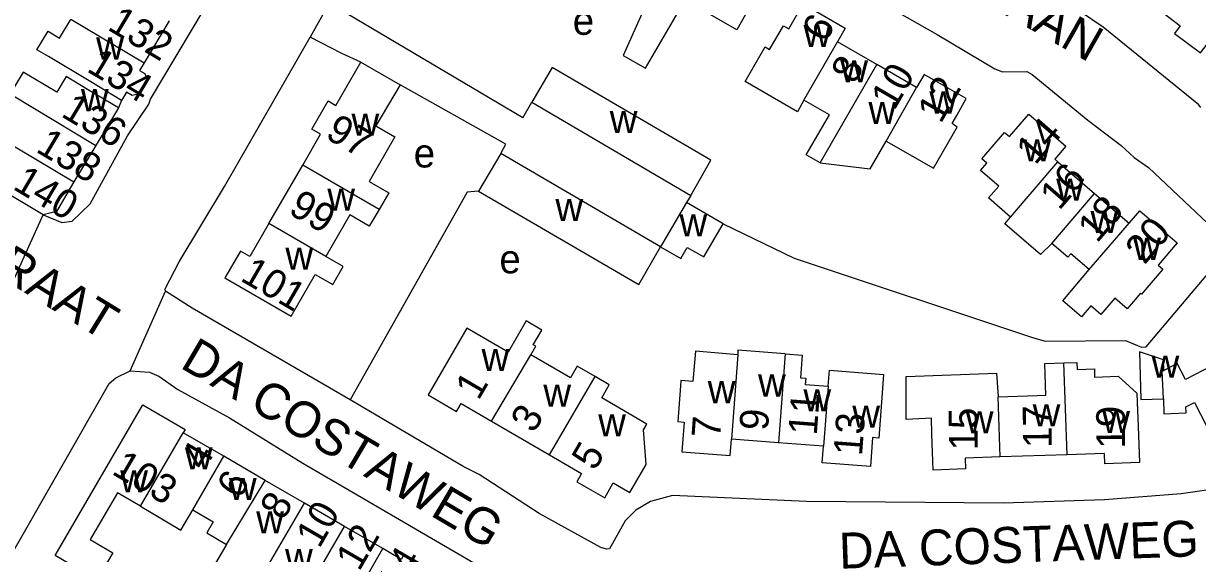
# Model space of a CAD drawing. Extents: x 159700 to 161346, y 381730 to 382922.
# Drawn here: x 160765.1 to 160928.7, y 382139.7 to 382213.5 of the extents above; entities that cross this region are included whole.
import ezdxf

# ---------------------------------------------------------------- set-up
doc = ezdxf.new("R2010")
doc.units = 0
for name, color, linetype in [('BLT_Basislijn', 7, 'Continuous'), ('BLT_Bebouwing', 7, 'Continuous'), ('BLT_Centroide', 7, 'Continuous'), ('BLT_Huisnummer', 7, 'Continuous'), ('BLT_Huisnummer_ tussenligend', 7, 'Continuous'), ('BLT_Onderverdeling_panden', 7, 'Continuous'), ('BLT_Straatnaam', 7, 'Continuous'), ('BLT_Vlakafsluiter', 7, 'Continuous')]:
    doc.layers.add(name, color=color, linetype=linetype)

msp = doc.modelspace()

# ---------------------------------------------------------------- linework, layer by layer
at = {"layer": 'BLT_Basislijn'}
for p, q in [((160807.74, 382216.28), (160805.06, 382211.58)), ((160834.7, 382200.34), (160807.74, 382216.28)), ((160778.79, 382202.76), (160778.34, 382201.7)), ((160834.7, 382200.34), (160835.95, 382202.49)), ((160826.96, 382189.98), (160810.64, 382161.06)), ((160828.54, 382190.12), (160826.96, 382189.98)), ((160858.09, 382189.53), (160857.51, 382188.55))]:
    msp.add_line(p, q, dxfattribs=at)
for points in [[(160767.85, 382186.82), (160770.48, 382185.77), (160771.9, 382185.95), (160774.4, 382188.34), (160779.62, 382197.8), (160782.59, 382202.23), (160782.84, 382202.92), (160792.24, 382218.76), (160803.22, 382237.82), (160806.44, 382242.83), (160810.55, 382250.26), (160817.15, 382261.02), (160835.05, 382295.51), (160838.75, 382303.93), (160849.94, 382327.61), (160850.64, 382329.04)], [(160930.26, 382281.92), (160914.44, 382254.38), (160914.14, 382253.57), (160909.42, 382245.95), (160905.84, 382238.9), (160900.19, 382229.43), (160898.69, 382226.67), (160898.35, 382225.67), (160912.26, 382215.21), (160915.57, 382213.01), (160928.68, 382202.38), (160929.12, 382201.78)], [(160828.73, 382252.07), (160829.72, 382251.88), (160832.18, 382250.64), (160855.26, 382237.21), (160858.7, 382235.39), (160869.71, 382228.86), (160872.45, 382227.61), (160873.32, 382226.88), (160874.69, 382222.21), (160875.39, 382221.63), (160892.46, 382211.94), (160900.47, 382207.13), (160901.54, 382206.71), (160904.95, 382206.79), (160905.68, 382206.37), (160913.45, 382200), (160918.08, 382196.48), (160919.9, 382194.81), (160921.88, 382193.4), (160933.46, 382182.5)], [(160784.93, 382176.17), (160784.88, 382176.49), (160786.8, 382180.26), (160793.12, 382190.75), (160805.06, 382211.58)], [(160812.13, 382208.09), (160809.48, 382209.26), (160805.06, 382211.58)], [(160831.62, 382195.36), (160832.34, 382196.65), (160817.6, 382204.91)], [(160862.63, 382185.55), (160872.52, 382180.8), (160905.59, 382169.8), (160907.5, 382169.24), (160918.66, 382169.32), (160920.93, 382168.39), (160921.57, 382168.42), (160933.46, 382182.5)], [(160810.64, 382161.06), (160788.65, 382173.82), (160784.93, 382176.17)], [(160762.83, 382138.43), (160777.07, 382163.35), (160777.98, 382164.11), (160779.97, 382165.1)], [(160779.97, 382165.1), (160782.68, 382164.9), (160783.96, 382164.37), (160786.64, 382162.49), (160793.84, 382158.54), (160804.07, 382152.25), (160827.87, 382138.34), (160829.56, 382136.57), (160829.84, 382135.46), (160829.82, 382132.85), (160829.69, 382132.32), (160817.98, 382111.93), (160815.18, 382106.64)], [(160946.11, 382155.27), (160943.66, 382152.45), (160939.58, 382150.34), (160930.62, 382148.56), (160926.43, 382147.98), (160915.76, 382147.11), (160901.7, 382146.68), (160874.21, 382146.92), (160855.55, 382147.72), (160852.49, 382146.89), (160850.46, 382145.69), (160848.98, 382144.21), (160846.78, 382140.3), (160846.37, 382140.25), (160845.56, 382140.51), (160836.96, 382145.22), (160828.6, 382150.66), (160826.49, 382151.73), (160810.64, 382161.06)]]:
    msp.add_lwpolyline(points, dxfattribs=at)
at = {"layer": 'BLT_Bebouwing'}
for p, q in [((160785.4, 382213.81), (160781.92, 382207.99)), ((160884.05, 382207.73), (160878.53, 382210.91)), ((160889.58, 382204.55), (160884.05, 382207.73)), ((160778.34, 382201.7), (160775.21, 382196.47)), ((160835.95, 382202.49), (160858.09, 382189.53)), ((160767.85, 382186.82), (160750.4, 382197.19)), ((160775.21, 382196.47), (160772.16, 382191.39)), ((160831.62, 382195.36), (160828.54, 382190.12)), ((160853.88, 382182.38), (160831.62, 382195.36)), ((160908.83, 382194.58), (160909.26, 382194.2)), ((160799.33, 382185.61), (160804.05, 382193.75)), ((160909.26, 382194.2), (160914.38, 382189.81)), ((160914.38, 382189.81), (160919.21, 382185.66)), ((160857.51, 382188.55), (160853.88, 382182.38)), ((160862.63, 382185.55), (160857.51, 382188.55)), ((160830.35, 382158.07), (160838.43, 382153.38)), ((160870.31, 382155.07), (160863.77, 382155.56)), ((160876.61, 382154.6), (160870.31, 382155.07)), ((160910.54, 382153.42), (160901.23, 382153.1))]:
    msp.add_line(p, q, dxfattribs=at)
for points in [[(160863.1, 382226.77), (160860.48, 382228.27), (160859.87, 382227.21), (160855.22, 382229.89), (160852.73, 382225.55), (160852.24, 382224.74), (160849.89, 382220.77), (160853.1, 382218.87), (160848.69, 382209.02), (160851.78, 382207.24), (160857.32, 382216.76)], [(160863.1, 382226.77), (160865.71, 382225.26), (160865.11, 382224.22), (160869.81, 382221.52), (160867.32, 382217.18), (160866.9, 382216.43), (160866.76, 382216.51), (160864.52, 382212.6), (160857.32, 382216.76)], [(160922.33, 382216.14), (160926.31, 382213.12), (160925.52, 382212.09), (160929.12, 382209.36), (160932.04, 382213.16), (160934.37, 382211.37), (160939.01, 382217.4), (160933.9, 382221.33), (160931.43, 382218.12), (160929.17, 382219.88), (160932.34, 382224.04), (160929.76, 382226), (160928.71, 382224.61)], [(160873.88, 382202.77), (160872.97, 382201.18), (160865.7, 382205.37), (160868.46, 382210.2), (160869.09, 382209.84), (160871.01, 382213.13), (160871.75, 382212.7), (160873.75, 382216.18), (160879.62, 382212.8), (160878.53, 382210.91)], [(160778.79, 382202.76), (160774.49, 382205.33), (160768.6, 382208.85), (160767, 382209.8), (160768.55, 382212.39), (160770.15, 382211.44), (160771.62, 382213.9)], [(160781.92, 382207.99), (160781.27, 382206.92), (160782.05, 382206.48), (160782.3, 382205.65), (160781.11, 382203.64), (160780.28, 382203.44), (160779.47, 382203.9), (160778.79, 382202.76)], [(160804.05, 382193.75), (160806.53, 382198.03), (160805.29, 382198.75), (160807.57, 382202.68), (160808.63, 382202.06), (160812.13, 382208.09)], [(160812.13, 382208.09), (160817.6, 382204.91)], [(160778.34, 382201.7), (160774.05, 382204.27), (160771.06, 382206.06), (160769.77, 382203.89), (160765.1, 382206.69), (160763.28, 382203.65)], [(160858.09, 382189.53), (160860.92, 382194.44), (160838.8, 382207.32), (160835.95, 382202.49)], [(160885.31, 382197.09), (160891.91, 382193.3), (160895.21, 382199.04), (160894.52, 382199.54), (160895.16, 382200.67), (160896.5, 382203), (160890.63, 382206.38), (160889.58, 382204.55)], [(160817.6, 382204.91), (160814.23, 382199.2), (160816.88, 382197.66), (160813.3, 382191.48), (160816.02, 382189.89), (160814.67, 382187.56)], [(160876.15, 382194.05), (160874.18, 382195.18), (160877.42, 382200.76), (160873.88, 382202.77)], [(160901.01, 382190.83), (160898.49, 382192.99), (160899.36, 382194), (160898.66, 382194.6), (160901.84, 382198.3), (160902.52, 382197.72), (160905.19, 382200.82), (160910.38, 382196.37), (160908.83, 382194.58)], [(160876.15, 382194.05), (160883.1, 382193.21), (160885.31, 382197.09)], [(160772.16, 382191.39), (160769.71, 382187.29), (160767.85, 382186.82)], [(160828.54, 382190.12), (160850.88, 382177.1), (160853.88, 382182.38)], [(160902.67, 382186.51), (160899.58, 382189.17), (160901.01, 382190.83)], [(160814.67, 382187.56), (160813.31, 382185.22), (160810.59, 382186.81), (160807.25, 382181.03)], [(160908.4, 382182.84), (160906.82, 382181.3), (160901.85, 382185.56), (160902.67, 382186.51)], [(160919.21, 382185.66), (160920.68, 382187.36), (160925.87, 382182.91), (160923.21, 382179.81), (160923.89, 382179.23), (160920.91, 382175.76), (160920.77, 382175.91), (160919.79, 382174.76), (160918.92, 382173.75), (160917.21, 382175.22), (160915.26, 382172.95), (160913.87, 382174.14), (160912.56, 382172.6), (160909.93, 382174.84), (160913.62, 382179.21)], [(160799.33, 382185.61), (160796.67, 382181.02), (160795.36, 382181.78), (160793.2, 382178.05), (160802.43, 382172.71), (160805.78, 382178.51), (160808.21, 382177.1), (160809.68, 382179.63), (160807.25, 382181.03)], [(160853.88, 382182.38), (160856.74, 382180.76), (160857.61, 382182.29), (160859.94, 382180.96), (160862.63, 382185.55)], [(160913.62, 382179.21), (160911.07, 382181.4), (160910.65, 382180.91), (160908.4, 382182.84)], [(160835.81, 382167.32), (160836.52, 382168.51), (160836.16, 382168.71), (160837.36, 382170.77), (160835.17, 382172.04), (160832.64, 382167.68), (160826.89, 382171.02), (160824.02, 382166.07), (160821.51, 382161.74), (160825.46, 382159.45), (160826.09, 382160.54), (160830.35, 382158.07)], [(160844.77, 382164.3), (160842.28, 382165.74), (160841.35, 382164.1), (160835.81, 382167.32)], [(160864.65, 382167.33), (160858.78, 382167.85), (160858.4, 382163.6), (160856.71, 382163.73), (160856.66, 382163.01), (160856.28, 382158.02), (160857.18, 382157.95), (160856.87, 382153.8), (160863.6, 382153.29), (160863.77, 382155.56)], [(160871.24, 382167.46), (160864.67, 382167.95), (160864.65, 382167.33)], [(160871.24, 382167.46), (160873.64, 382167.28), (160873.4, 382164.12), (160874.13, 382164.06), (160874.06, 382163.19), (160877.24, 382162.97)], [(160924.01, 382165.16), (160923.96, 382166.61), (160920.61, 382167.73), (160920.84, 382161.08), (160923.96, 382161.18)], [(160933.31, 382167.12), (160927.03, 382163.87), (160925.87, 382166.12), (160924.01, 382165.16)], [(160877.24, 382162.97), (160877.42, 382165.17), (160884.97, 382164.59), (160884.68, 382160.71), (160884.31, 382155.72), (160883.43, 382155.79), (160883.13, 382151.77), (160876.43, 382152.28), (160876.61, 382154.6)], [(160900.94, 382161.48), (160906.35, 382161.67), (160907.57, 382161.71), (160907.42, 382166.11), (160910.09, 382166.2)], [(160910.09, 382166.2), (160911.89, 382166.26), (160911.96, 382165.27), (160914.34, 382165.36), (160914.38, 382164.23), (160917.64, 382164.35), (160920.25, 382162), (160920.3, 382160.73), (160920.44, 382157.32), (160920.61, 382152.32), (160915.81, 382152.16), (160915.76, 382153.6), (160910.54, 382153.42)], [(160838.43, 382153.38), (160842.89, 382150.79), (160842.23, 382149.65), (160846.11, 382147.4), (160847.3, 382149.51), (160849.61, 382148.13), (160851.9, 382152.03), (160851.5, 382156.9), (160851.98, 382157.69), (160845.69, 382161.34), (160846.73, 382163.15), (160844.77, 382164.3)], [(160901.23, 382153.1), (160896.34, 382152.93), (160896.4, 382151.43), (160891.89, 382151.28), (160891.71, 382156.27), (160891.63, 382158.5), (160888.11, 382158.31), (160888.14, 382164.32), (160900.72, 382164.77), (160900.94, 382161.48)], [(160781.42, 382146.23), (160778.2, 382148.11), (160774.4, 382141.59), (160777.55, 382139.75), (160775.34, 382135.97), (160773.84, 382136.84), (160769.52, 382139.36), (160781.77, 382160.35), (160787.63, 382156.93), (160787.38, 382156.48)], [(160923.96, 382161.18), (160924.03, 382159.12), (160927.12, 382159.23), (160927.09, 382160.09), (160928.29, 382160.7), (160930.86, 382155.71), (160937.41, 382159.17)], [(160793.03, 382153.19), (160787.38, 382156.48)], [(160798.79, 382149.83), (160793.03, 382153.19)], [(160804.26, 382146.65), (160798.79, 382149.83)], [(160781.42, 382146.23), (160787.06, 382142.93), (160788.7, 382145.74)], [(160788.7, 382145.74), (160791.55, 382144.07), (160790.66, 382142.53), (160793.41, 382140.93)], [(160809.84, 382143.44), (160804.26, 382146.65)], [(160815.2, 382140.34), (160809.84, 382143.44)], [(160793.41, 382140.93), (160790.82, 382136.49), (160793.74, 382134.79), (160795.74, 382138.21), (160798.45, 382136.63)], [(160821.09, 382137.55), (160818.05, 382139.32), (160817.77, 382138.84), (160815.2, 382140.34)]]:
    msp.add_lwpolyline(points, dxfattribs=at)
at = {"layer": 'BLT_Onderverdeling_panden'}
for p, q in [((160873.88, 382202.77), (160878.53, 382210.91)), ((160876.15, 382194.05), (160884.05, 382207.73)), ((160885.31, 382197.09), (160889.58, 382204.55)), ((160763.28, 382203.65), (160775.21, 382196.47)), ((160814.67, 382187.56), (160804.05, 382193.75)), ((160902.67, 382186.51), (160909.26, 382194.2)), ((160908.4, 382182.84), (160914.38, 382189.81)), ((160807.25, 382181.03), (160799.33, 382185.61)), ((160913.62, 382179.21), (160919.21, 382185.66)), ((160830.35, 382158.07), (160835.81, 382167.32)), ((160864.65, 382167.33), (160863.77, 382155.56)), ((160871.24, 382167.46), (160870.31, 382155.07)), ((160910.54, 382153.42), (160910.09, 382166.2)), ((160838.43, 382153.38), (160844.77, 382164.3)), ((160877.24, 382162.97), (160876.61, 382154.6)), ((160901.23, 382153.1), (160900.94, 382161.48)), ((160781.42, 382146.23), (160787.38, 382156.48)), ((160788.7, 382145.74), (160793.03, 382153.19)), ((160793.41, 382140.93), (160798.79, 382149.83)), ((160798.45, 382136.63), (160804.26, 382146.65)), ((160804.22, 382133.73), (160809.84, 382143.44)), ((160809.33, 382130.23), (160815.2, 382140.34))]:
    msp.add_line(p, q, dxfattribs=at)
for points in [[(160771.62, 382213.9), (160771.73, 382214.08), (160781.92, 382207.99)], [(160750.4, 382197.19), (160753.55, 382202.45), (160772.16, 382191.39)], [(160923.96, 382161.18), (160923.8, 382165.05), (160924.01, 382165.16)]]:
    msp.add_lwpolyline(points, dxfattribs=at)
at = {"layer": 'BLT_Vlakafsluiter'}
for p, q in [((160762.16, 382174.21), (160767.85, 382186.82)), ((160779.97, 382165.1), (160784.93, 382176.17))]:
    msp.add_line(p, q, dxfattribs=at)

# ---------------------------------------------------------------- texts
at = {"layer": 'BLT_Centroide'}
for s, p in [('e', (160841.66, 382211.88)), ('w', (160873.81, 382210.19)), ('w', (160775.25, 382208.44)), ('w', (160878.94, 382205.28)), ('w', (160773.13, 382201.25)), ('w', (160882.86, 382199.47)), ('w', (160891.36, 382200.92)), ('w', (160810.83, 382197.83)), ('w', (160846.81, 382198.19)), ('e', (160819.5, 382193.41)), ('w', (160904.44, 382194.25)), ('w', (160909.03, 382188.77)), ('w', (160807.46, 382187.41)), ('w', (160839.24, 382185.94)), ('w', (160856.53, 382183.81)), ('w', (160913.8, 382184.3)), ('w', (160919.75, 382180.55)), ('w', (160801.62, 382179.16)), ('e', (160831.44, 382178.67)), ('w', (160828.95, 382165.06)), ('w', (160922.31, 382164.14)), ('w', (160860.47, 382160.59)), ('w', (160867.48, 382161.52)), ('w', (160837.56, 382160.09)), ('w', (160873.8, 382159.45)), ('w', (160880.61, 382157.17)), ('w', (160905.74, 382157.38)), ('w', (160845.2, 382155.98)), ('w', (160896.42, 382156.38)), ('w', (160915.45, 382156.44)), ('w', (160787.61, 382151.36)), ('w', (160778.6, 382148.16)), ('w', (160793.75, 382147.12)), ('w', (160797.55, 382142.45)), ('w', (160801.57, 382137.2))]:
    msp.add_text(s, height=4, dxfattribs=at).set_placement(p)
at = {"layer": 'BLT_Huisnummer'}
for s, rotation, p in [('6', 59.9094, (160876.84, 382210.64)), ('134', 329.1109, (160773.79, 382206.87)), ('12', 60.1038, (160892.93, 382199.39)), ('97', 329.9134, (160807.01, 382197.6)), ('14', 49.0923, (160906.11, 382193.63)), ('138', 329.2759, (160766.69, 382195.68)), ('140', 329.2729, (160763.47, 382190.49)), ('20', 49.3484, (160921.33, 382179.77)), ('101', 329.9153, (160795.18, 382177.73)), ('1', 59.7538, (160828.52, 382160.85)), ('19', 90.2314, (160918.62, 382154.28)), ('7', 85.6943, (160862.18, 382155.63)), ('13', 85.6988, (160881.96, 382153.18)), ('15', 90.6671, (160898.09, 382154.04)), ('4', 59.8657, (160790.31, 382151.07)), ('5', 59.8633, (160844.74, 382151.03)), ('103', 329.7082, (160777.26, 382150.81)), ('8', 59.8668, (160801.31, 382144.12)), ('10', 59.8668, (160806.33, 382140.24)), ('14', 59.8698, (160817.7, 382133.87))]:
    msp.add_text(s, height=4, rotation=rotation, dxfattribs=at).set_placement(p)
at = {"layer": 'BLT_Huisnummer_ tussenligend'}
for s, rotation, p in [('132', 329.1096, (160776.67, 382212.69)), ('8', 59.9094, (160880.88, 382204.86)), ('10', 59.9094, (160886.45, 382201.22)), ('136', 329.1109, (160770.21, 382200.6)), ('16', 49.0923, (160909.44, 382187.32)), ('99', 329.9134, (160801.87, 382187.07)), ('18', 49.0923, (160914.7, 382182.77)), ('11', 85.6943, (160875.65, 382156.04)), ('3', 59.7594, (160836.24, 382156.28)), ('17', 90.6671, (160908.42, 382154.38)), ('9', 85.6943, (160868.84, 382156.69)), ('6', 59.8657, (160795.29, 382147.08)), ('12', 59.8649, (160811.89, 382137.05))]:
    msp.add_text(s, height=4, rotation=rotation, dxfattribs=at).set_placement(p)
at = {"layer": 'BLT_Straatnaam'}
for s, rotation, p in [('HUIJGENSLAAN', 330.4263, (160868.99, 382233.31)), ('JAN VAN DER NOOTSTRAAT', 328.44, (160698.04, 382217.27)), ('DA COSTAWEG', 329.44, (160786.79, 382165.62)), ('DA COSTAWEG', 2.0131, (160878.84, 382137.53))]:
    msp.add_text(s, height=5, rotation=rotation, dxfattribs=at).set_placement(p)

doc.saveas('drawing.dxf')
